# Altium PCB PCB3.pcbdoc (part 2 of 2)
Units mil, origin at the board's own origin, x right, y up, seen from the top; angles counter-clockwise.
Board outline 2248.24 x 2229.86 mil, 2 copper layers (Top Layer, Bottom Layer); 104 components, 71 nets, 405 pads, 227 vias.
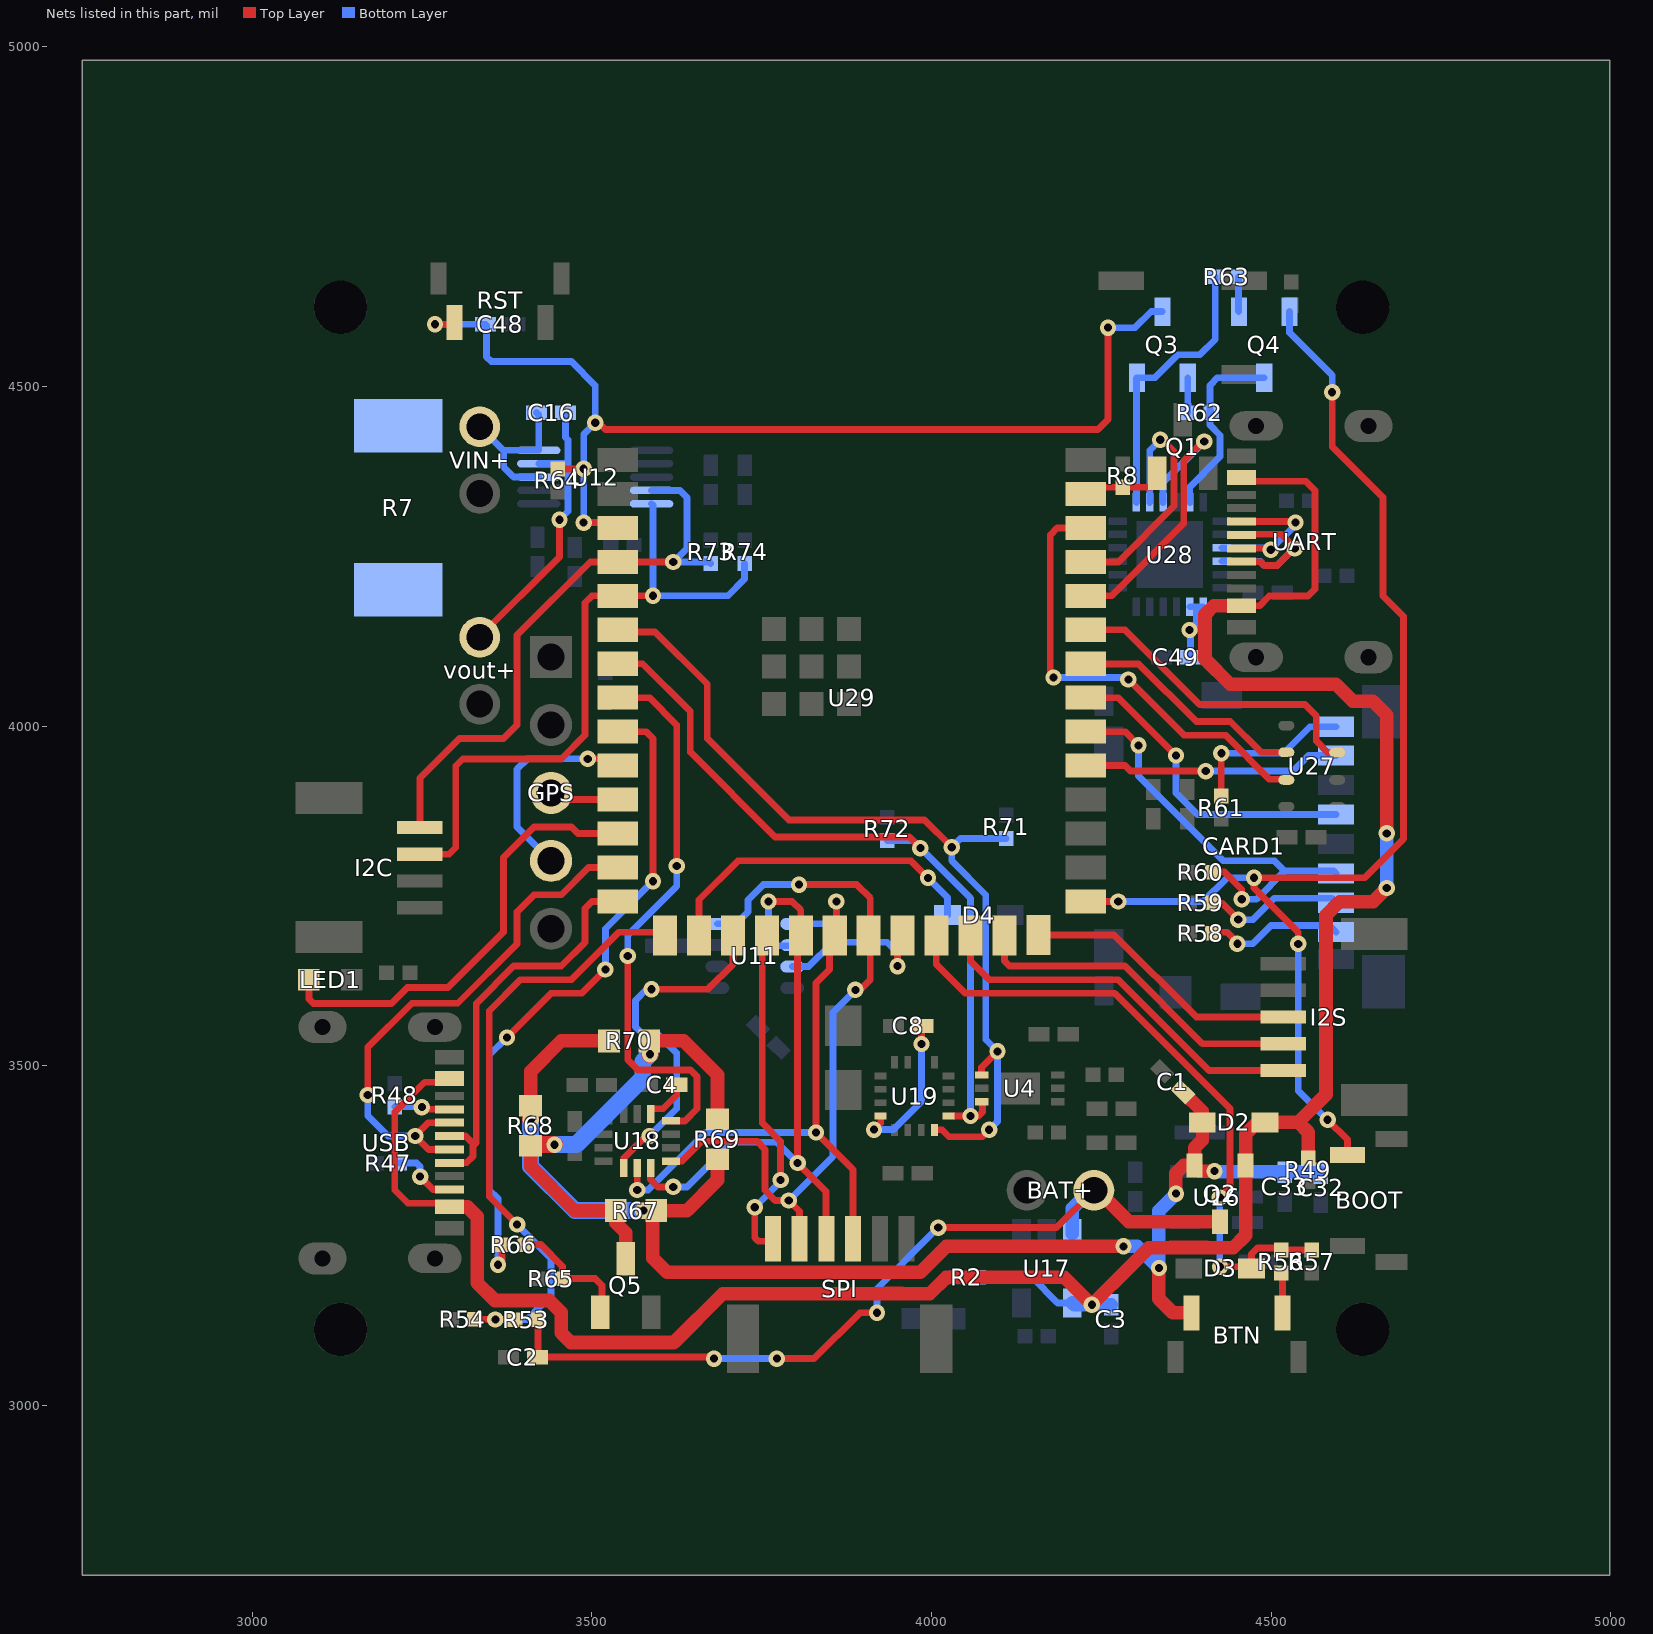
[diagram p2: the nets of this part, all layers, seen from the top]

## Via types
v1: diameter 24.02, hole 12.01, Top Layer to Bottom Layer, 222 vias
v2: diameter 24, hole 12, Top Layer to Bottom Layer, 5 vias

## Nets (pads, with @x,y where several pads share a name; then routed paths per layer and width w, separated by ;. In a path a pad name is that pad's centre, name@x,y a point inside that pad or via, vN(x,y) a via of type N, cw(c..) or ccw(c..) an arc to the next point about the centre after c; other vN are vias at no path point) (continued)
$1N23529: C4.1 U18.5 | length 69.9
  Top Layer w10: U18.5@3586.36,3428.94 3586.36,3436.5 3604.88,3436.5 3624.96,3456.58 C4.1@3624.96,3472.02
$1N25668: R48.1 USB.4 | length 82.1
  Top Layer w10: v1(3249.71,3438.84) 3252.85,3435.7 USB.4@3290.39,3435.7
  Bottom Layer w10: R48.1@3209.88,3439.46 3249.1,3439.46 v1(3249.71,3438.84)
$1N25676: R47.1 USB.10 | length 98.4
  Top Layer w10: v1(3247.06,3336.5) 3265.96,3317.59 USB.10@3290.39,3317.59
  Bottom Layer w10: R47.1@3216.92,3356.5 3242.06,3356.5 3247.06,3351.5 v1(3247.06,3336.5)
$1N26665: Q3.1 R62.2 | length 51.6
  Bottom Layer w10: Q3.1@4377.28,4512.87 4377.28,4462.06 R62.2@4377.84,4461.5
$1N26669: Q4.1 R63.2 | length 51.6
  Bottom Layer w10: R63.2@4451.92,4661.5 4451.92,4610.68 Q4.1@4452.48,4610.12
$1N33198: D4.2 U29.16 | length 491.2
  Top Layer w10: U29.16@3657.56,3691.3 3657.56,3744.18 3714.88,3801.5 3969.85,3801.5 v1(3994.87,3776.48)
  Bottom Layer w10: v1(3994.87,3776.48) 4023.72,3747.63 D4.2@4023.72,3721.5
$1N33595: BTN.1 R56.1 | length 59.4
  Top Layer w10: R56.1@4514.88,3194.46 4516.74,3192.61 BTN.1@4516.74,3135.84
$1N42658: Q5.1 R65.1 R66.2 | length 188.7
  Top Layer w10: R66.2@3401.92,3236.5 3424.88,3236.5 3456.92,3204.46 R65.1@3456.92,3186.5 3504.88,3186.5 3514.88,3176.5 3514.88,3139.53 Q5.1@3512.48,3137.13
$1N45866: Q5.3 R67.1 R68.1 R69.1 R70.1 | length 711.9
  Top Layer w20: R68.1@3409.88,3381.84 3409.88,3351.5 3474.88,3286.5 R67.1@3535.22,3286.5 3535.22,3268.76 3549.88,3254.1 Q5.3@3549.88,3215.87 ; R70.1@3584.54,3536.5 3634.88,3536.5 3684.88,3486.5 R69.1@3684.88,3421.16
  Top Layer w25: R68.1@3409.88,3381.84 3411.56,3383.51 v1(3444.88,3383.51) ; R70.1@3584.54,3536.5 3585.66,3535.38 v1(3585.66,3516.63)
  Bottom Layer w25: v1(3444.88,3383.51) 3476.9,3383.51 3574.88,3481.5 3574.88,3505.85 v1(3585.66,3516.63)
BUZZER: Q1.1 R8.2 U29.39 | length 125.6
  Top Layer w10: U29.39@4227.05,4341.69 4235.08,4341.69 4244.88,4351.5 R8.2@4281.84,4351.5 ; R8.2@4281.88,4351.46 4324.84,4351.46 4332.48,4359.1 Q1.1@4332.48,4372.13
CS: U18.12 U29.17 | length 527.5
  Top Layer w10: U18.12@3546.99,3349.22 3546.99,3363.87 3579.63,3396.5 v1(3584.88,3396.5) ; v1(3587.88,3612.5) 3670.88,3612.5 3707.56,3649.18 U29.17@3707.56,3691.3
  Bottom Layer w10: v1(3584.88,3396.5) 3624.88,3436.5 3624.88,3518.51 3596.89,3546.5 3574.88,3546.5 3564.35,3557.03 3564.35,3596.07 3580.78,3612.5 v1(3587.88,3612.5)
CS1: U11.2 U29.22 | length 243.9
  Top Layer w10: v1(3949.88,3646.5) 3949.88,3683.63 U29.22@3957.56,3691.3
  Bottom Layer w10: U11.2@3795,3645.75 3819.13,3645.75 3854.88,3681.5 3934.88,3681.5 3949.88,3666.5 v1(3949.88,3646.5)
CS2: SPI.1 U29.18 | length 504.7
  Top Layer w10: v1(3739.88,3291.5) 3739.88,3246.5 3744.88,3241.5 3762.84,3241.5 SPI.1@3766.46,3245.12 ; U29.18@3757.56,3691.3 3750.87,3684.61 3750.87,3415.51 3777.88,3388.51 v1(3777.88,3331.5)
  Bottom Layer w10: v1(3739.88,3291.5) 3777.88,3329.49 v1(3777.88,3331.5)
D+: U28.3 UART.6 UART.8 | length 252.1
  Top Layer w10: UART.6@4456.38,4261.65 4497.23,4261.65 v2(4499.39,4259.5) ; UART.8@4456.38,4301.02 4534.36,4301.02 v2(4535.88,4299.5)
  Bottom Layer w10: U28.3@4427.66,4262.34 4496.54,4262.34 v2(4499.39,4259.5) 4535.88,4296 v2(4535.88,4299.5)
D-: U28.4 UART.5 UART.7 | length 299.5
  Top Layer w10: UART.5@4456.38,4241.97 4484.41,4241.97 4489.87,4236.51 4508.91,4236.51 4533.89,4261.5 v2(4534.88,4261.5) 4534.88,4262.48 4514.88,4282.48 4457.52,4282.48 UART.7@4456.38,4281.34
  Bottom Layer w10: U28.4@4427.66,4242.65 4483.73,4242.65 4489.87,4236.51 4508.91,4236.51 4533.89,4261.5 v2(4534.88,4261.5)
DATA0: CARD1.7 U29.31 | length 381.6
  Top Layer w10: U29.31@4227.05,3941.69 4285.08,3941.69 4293.2,3933.57 v1(4403.75,3933.57)
  Bottom Layer w10: v1(4403.75,3933.57) 4531.96,3933.57 4554.88,3956.5 4595.62,3956.5 CARD1.7@4595.71,3956.4
DATA1: CARD1.8 R61.2 | length 248.1
  Top Layer w10: R61.2@4426.74,3896.94 v1(4426.74,3959.9)
  Bottom Layer w10: v1(4426.74,3959.9) 4518.29,3959.9 4557.29,3998.9 CARD1.8@4595.71,3998.9
DATA2: CARD1.1 R58.2 | length 211.3
  Top Layer w10: R58.2@4413.78,3689.9 4413.78,3695.4 4414.88,3696.5 4434.88,3696.5 4450.34,3681.05 v1(4450.34,3679.39)
  Bottom Layer w10: v1(4450.34,3679.39) 4472.77,3679.39 4499.88,3706.5 4585.72,3706.5 CARD1.1@4595.71,3696.5
DATA3: CARD1.2 R59.2 | length 208.1
  Top Layer w10: R59.2@4413.78,3739.9 4426.74,3739.9 v1(4451.74,3714.9)
  Bottom Layer w10: v1(4451.74,3714.9) 4473.29,3714.9 4504.88,3746.5 4589.02,3746.5 CARD1.2@4595.71,3739.8
DTR: Q4.3 R62.1 U28.23 | length 283.7
  Bottom Layer w10: U28.23@4380.42,4329.27 4379.88,4329.81 4379.88,4351.5 4424.88,4396.5 4424.88,4428.08 4409.88,4443.08 4409.88,4459.46 R62.1@4411.92,4461.5 4409.88,4463.54 4409.88,4501.5 4421.26,4512.87 Q4.3@4489.88,4512.87
ESP_D+: U29.14 USB.6 USB.8 | length 608.7
  Top Layer w10: USB.8@3290.39,3356.97 3315.3,3356.97 3324.82,3366.5 3324.82,3381.44 3329.88,3386.5 ; USB.6@3290.39,3396.34 3313.79,3396.34 3323.64,3386.5 3329.88,3386.5 ; U29.14@3538.07,3741.69 3500.08,3741.69 3489.88,3731.5 3489.88,3681.5 3454.88,3646.5 3384.88,3646.5 3329.88,3591.5 3329.88,3386.5
ESP_D-: U29.13 USB.5 USB.7 | length 805.5
  Top Layer w10: v1(3169.88,3456.79) 3169.88,3526.5 3235.18,3591.79 3302.5,3591.79 3389.88,3679.17 3389.88,3726.5 3414.88,3751.5 3454.88,3751.5 3495.08,3791.69 U29.13@3538.07,3791.69 ; USB.7@3290.39,3376.65 3259.73,3376.65 v1(3239.88,3396.5) 3259.41,3416.02 USB.5@3290.39,3416.02
  Bottom Layer w10: v1(3169.88,3456.79) 3169.88,3426.5 3199.88,3396.5 v1(3239.88,3396.5)
ESP_IO0: BOOT.1 Q4.2 U29.27 | length 1816.7
  Top Layer w10: U29.27@4227.05,3741.69 4274.69,3741.69 v1(4274.88,3741.5) ; v1(4539.88,3679.28) 4539.88,3696.5 4474.88,3761.5 v1(4474.88,3776.5) 4637.4,3776.5 4694.88,3833.98 4694.88,4161.5 4664.88,4191.5 4664.88,4336.5 4589.88,4411.5 v1(4589.88,4491.5) ; v1(4583.18,3420.21) 4612.33,3391.05 BOOT.1@4612.33,3368.5
  Bottom Layer w10: v1(4274.88,3741.5) 4399.88,3741.5 4434.88,3776.5 v1(4474.88,3776.5) ; Q4.2@4527.28,4610.12 4527.28,4579.1 4589.88,4516.5 v1(4589.88,4491.5) ; v1(4539.88,3679.28) 4539.88,3463.5 v1(4583.18,3420.21)
ESP_RST: C48.1 Q3.3 R64.2 RST.1 U29.3 | length 1621.3
  Top Layer w10: v1(3268.87,4591.5) 3295.43,4591.5 RST.1@3297.95,4594.02 ; R64.2@3449.88,4378.54 3487.66,4378.54 v1(3487.88,4378.76) ; v1(3487.88,4299.49) 3530.27,4299.49 U29.3@3538.07,4291.69 ; v1(3504.88,4446.5) 3509.88,4446.5 3519.88,4436.5 4244.88,4436.5 4259.88,4451.5 v1(4259.88,4586.5)
  Bottom Layer w10: v1(3268.87,4591.5) C48.1@3343.42,4591.5 3344.88,4590.04 3344.88,4543.57 3351.96,4536.5 3469.88,4536.5 3504.88,4501.5 v1(3504.88,4446.5) 3487.88,4429.49 v1(3487.88,4378.76) v1(3487.88,4299.49) ; v1(4259.88,4586.5) 4299.88,4586.5 4323.51,4610.12 Q3.3@4339.88,4610.12
ESP_RXD: U28.21 U29.36 | length 437.3
  Top Layer w10: U29.36@4227.05,4191.69 4265.08,4191.69 4371.26,4297.88 4371.26,4390.03 4400.05,4418.81 v2(4401.65,4418.81)
  Bottom Layer w10: U28.21@4341.05,4329.27 4341.05,4358.21 v2(4401.65,4418.81)
ESP_TXD: U28.20 U29.37 | length 370.7
  Top Layer w10: U29.37@4227.05,4241.69 4275.08,4241.69 4357.25,4323.86 4357.25,4404.14 4339.88,4421.5 v2(4336.88,4421.5)
  Bottom Layer w10: U28.20@4321.36,4329.27 4321.36,4405.97 v2(4336.88,4421.5)
GND: 
HEAT: R66.1 U29.9 | length 994.3
  Top Layer w10: v1(3361.84,3206.87) 3367.84,3212.87 R66.1@3367.84,3236.5 ; v1(3374.88,3541.5) 3439.88,3606.5 3484.88,3606.5 v1(3519.88,3641.5) ; U29.9@3538.07,3991.69 3579.69,3991.69 3589.88,3981.5 v1(3589.88,3771.5)
  Bottom Layer w10: v1(3361.84,3206.87) 3361.84,3304.25 3348.9,3317.19 3348.9,3515.51 v1(3374.88,3541.5) ; v1(3519.88,3641.5) 3519.88,3701.5 v1(3589.88,3771.5)
I2S1_DAT: I2S.1 U29.24 | length 564.6
  Top Layer w10: U29.24@4057.56,3691.3 4057.56,3653.82 4084.88,3626.5 4274.88,3626.5 4408.62,3492.76 I2S.1@4517.95,3492.76
I2S1_SCK: I2S.2 U29.25 | length 498.3
  Top Layer w10: U29.25@4107.56,3691.3 4107.56,3653.82 4114.88,3646.5 4284.88,3646.5 4399.25,3532.13 I2S.2@4517.95,3532.13
I2S1_WS: I2S.3 U29.26 | length 410.5
  Top Layer w10: U29.26@4157.56,3692.48 4268.9,3692.48 4389.88,3571.5 I2S.3@4517.95,3571.5
I2S_DAT: U27.7 U29.38 | length 673.8
  Top Layer w10: v1(4179.53,4071.5) 4174.88,4076.15 4174.88,4281.5 4185.08,4291.69 U29.38@4227.05,4291.69 ; v1(4289.88,4068.51) 4371.89,3986.5 4432.66,3986.5 4497.66,3921.5 4521.58,3921.5 U27.7@4522.48,3920.6
  Bottom Layer w10: v1(4179.53,4071.5) 4286.89,4071.5 v1(4289.88,4068.51)
I2S_SCK: U27.6 U29.34 | length 349.5
  Top Layer w10: U29.34@4227.05,4091.69 4227.25,4091.5 4304.88,4091.5 4389.88,4006.5 4439.88,4006.5 4484.88,3961.5 4522.18,3961.5 U27.6@4522.48,3961.2
I2S_WS: U27.3 U29.35 | length 466.7
  Top Layer w10: U29.35@4227.05,4141.69 4284.69,4141.69 4394.88,4031.5 4549.88,4031.5 4566.6,4014.78 4566.6,3977.74 4583.14,3961.2 U27.3@4597.28,3961.2
INT1: U18.4 U29.8 | length 831.9
  Top Layer w10: U29.8@3538.07,4041.69 3584.69,4041.69 3624.88,4001.5 v1(3624.88,3793.82) ; v1(3552.68,3661.5) 3552.68,3508.7 3567.75,3493.63 3645.06,3493.63 3654.88,3483.81 3654.88,3436.5 3637,3418.61 U18.4@3616.36,3418.61
  Bottom Layer w10: v1(3552.68,3661.5) 3552.68,3691.78 3624.88,3763.98 v1(3624.88,3793.82)
KEY: D3.2 R56.2 R57.1 U29.23 | length 964.4
  Top Layer w10: U29.23@4007.56,3691.3 4006.88,3690.63 4006.88,3649.5 4049.88,3606.5 4269.88,3606.5 4439.69,3436.69 4439.69,3321.02 v1(4424.54,3305.86) ; v1(4424.71,3203.95) 4468.6,3203.95 D3.2@4471.05,3201.5 4471.05,3222.66 4479.88,3231.5 4511.92,3231.5 R56.2@4514.88,3228.54 R57.1@4559.88,3228.54
  Bottom Layer w10: v1(4424.54,3305.86) 4424.54,3204.12 v1(4424.71,3203.95)
LED: LED1.1 U29.12 | length 661.9
  Top Layer w10: LED1.1@3083.4,3626.37 3083.4,3597.98 3089.88,3591.5 3204.88,3591.5 3228.27,3614.88 3288.27,3614.88 3369.88,3696.5 3369.88,3806.5 3414.88,3851.5 3469.88,3851.5 3479.69,3841.69 U29.12@3538.07,3841.69
MISO: SPI.2 U11.5 U18.1 U29.21 | length 1088.3
  Top Layer w10: U18.1@3616.36,3359.55 3632.94,3359.55 3662.08,3388.7 3742.89,3388.7 3754.88,3376.71 3754.88,3316.5 3769.88,3301.5 v1(3789.88,3301.5) 3805.83,3285.55 SPI.2@3805.83,3245.12 ; v1(3804.88,3766.5) 3889.88,3766.5 3909.88,3746.5 3909.88,3693.63 U29.21@3907.56,3691.3 3909.88,3688.98 3909.88,3626.5 3894.88,3611.5 v1(3887.88,3611.5)
  Bottom Layer w10: U11.5@3684.77,3708.74 3712.12,3708.74 3729.88,3726.5 3729.88,3744.01 3752.37,3766.5 v1(3804.88,3766.5) ; v1(3789.88,3301.5) 3854.88,3366.5 3854.88,3578.51 v1(3887.88,3611.5)
MOSI: SPI.3 U11.3 U18.14 U29.19 | length 928.3
  Top Layer w10: U18.14@3586.36,3349.22 3586.36,3332.49 3597.36,3321.5 v1(3619.88,3321.5) ; v1(3759.88,3741.5) 3794.88,3741.5 3807.56,3728.82 U29.19@3807.56,3691.3 3802.88,3686.62 v1(3802.88,3356.5) 3844.88,3314.49 3844.88,3245.44 SPI.3@3845.2,3245.12
  Bottom Layer w10: v1(3619.88,3321.5) 3639.88,3321.5 3705.42,3387.03 3772.34,3387.03 v1(3802.88,3356.5) ; v1(3759.88,3741.5) 3759.88,3686.5 3769.88,3676.5 3794.25,3676.5 U11.3@3795,3677.25
RTS: Q3.2 R63.1 U28.19 | length 414.8
  Bottom Layer w10: U28.19@4301.68,4329.27 4301.68,4512.07 Q3.2@4302.48,4512.87 4328.88,4512.87 4362.5,4546.5 4394.88,4546.5 4417.84,4569.46 R63.1@4417.84,4661.5
RXD: GPS.3 U29.11 | length 102.2
  Top Layer w10: GPS.3@3439.88,3901.5 3449.69,3891.69 U29.11@3538.07,3891.69
SCL: R72.1 U4.6 U19.1 U29.7 | length 1140
  Top Layer w10: U29.7@3538.07,4091.69 3574.69,4091.69 3644.88,4021.5 3644.88,3961.5 3769.88,3836.5 3967.37,3836.5 v1(3983.63,3820.24) ; U19.1@4024.7,3425.73 v1(4057.36,3425.73) 4069.11,3425.73 4074.88,3431.5 4074.88,3445.61 U4.6@4073.68,3446.81
  Bottom Layer w10: R72.1@3934.88,3831.46 3972.41,3831.46 v1(3983.63,3820.24) 4057.36,3746.51 v1(4057.36,3425.73)
SCL1: I2C.2 R74.2 U12.5 U29.5 | length 989.6
  Top Layer w10: I2C.2@3246.81,3811.18 3289.56,3811.18 3299.56,3821.18 3299.56,3941.18 3309.88,3951.5 3454.88,3951.5 3489.88,3986.5 3489.88,4181.5 3500.08,4191.69 U29.5@3538.07,4191.69 3589.78,4191.69 v1(3589.88,4191.8)
  Bottom Layer w10: U12.5@3587.95,4327.13 3589.88,4325.2 v1(3589.88,4191.8) 3700.18,4191.8 3724.88,4216.5 R74.2@3724.88,4239.46
SCLK: SPI.4 U11.4 U18.13 U29.20 | length 955
  Top Layer w10: v1(3566.68,3317) U18.13@3566.68,3349.22 ; v1(3859.88,3741.5) 3859.88,3693.63 U29.20@3857.56,3691.3 3849.88,3683.63 3849.88,3641.5 3829.88,3621.5 v1(3829.88,3401.5) 3884.57,3346.81 SPI.4@3884.57,3245.12
  Bottom Layer w10: v1(3566.68,3317) 3582.87,3317 3667.37,3401.5 v1(3829.88,3401.5) ; U11.4@3795,3708.74 3852.12,3708.74 3859.88,3716.5 v1(3859.88,3741.5)
SD_CMD: CARD1.3 R60.2 U29.32 | length 630
  Top Layer w10: U29.32@4227.05,3991.69 4284.69,3991.69 v1(4304.88,3971.5) ; R60.2@4413.78,3784.9 4431.48,3784.9 4456.74,3759.64 v1(4456.74,3744.9)
  Bottom Layer w10: v1(4304.88,3971.5) 4304.88,3926.5 4429.88,3801.5 4504.88,3801.5 4519.88,3786.5 ; v1(4456.74,3744.9) 4478.29,3744.9 4519.88,3786.5 ; CARD1.3@4595.71,3783.1 4592.32,3786.5 4519.88,3786.5
SD_SCLK: CARD1.5 U29.33 | length 472.1
  Top Layer w10: U29.33@4227.05,4041.69 4274.69,4041.69 v1@4359.82,3956.56
  Bottom Layer w10: v1(4359.88,3956.56) 4359.88,3901.5 4391.58,3869.8 CARD1.5@4595.71,3869.8
SDA: R71.1 U4.4 U19.16 U29.6 | length 1339.1
  Top Layer w10: U29.6@3538.07,4141.69 3541.2,4138.57 3592.81,4138.57 3669.88,4061.5 3669.88,3981.5 3789.88,3861.5 3989.88,3861.5 v1(4029.88,3821.5) ; U19.16@4004.51,3405.53 4015.85,3405.53 4026.18,3395.21 4074.56,3395.21 v1(4084.88,3405.53) ; U4.4@4073.68,3486.18 4073.68,3497.48 v1(4097.19,3520.99)
  Bottom Layer w10: v1(4084.88,3405.53) 4097.19,3417.83 v1(4097.19,3520.99) 4079.88,3538.3 4079.88,3751.5 4029.88,3801.5 v1(4029.88,3821.5) 4042.84,3834.46 R71.1@4109.88,3834.46
SDA1: I2C.1 R73.2 U12.4 U29.4 | length 870.8
  Top Layer w10: I2C.1@3246.81,3850.55 3246.81,3923.43 3304.88,3981.5 3369.88,3981.5 3389.88,4001.5 3389.88,4133.96 3497.62,4241.69 U29.4@3538.07,4241.69 3619.69,4241.69 v1(3619.88,4241.5)
  Bottom Layer w10: U12.4@3587.95,4346.81 3629.57,4346.81 3639.88,4336.5 3639.88,4261.5 v1(3619.88,4241.5) 3672.84,4241.5 R73.2@3674.88,4239.46
SETC: C8.2 U19.12 | length 223.3
  Top Layer w10: v1(3915.31,3405.79) 3925.25,3415.73 U19.12@3925.25,3425.72 ; v1(3985.31,3531.83) 3985.31,3556.45 C8.2@3987.22,3558.36
  Bottom Layer w10: v1(3915.31,3405.79) 3944.17,3405.79 3985.31,3446.93 v1(3985.31,3531.83)
TXD: GPS.4 U29.10 | length 314.3
  Top Layer w10: v1(3493.88,3951.66) 3528.03,3951.66 U29.10@3538.03,3941.66
  Bottom Layer w10: GPS.4@3439.88,3801.5 3389.88,3851.5 3389.88,3936.5 3405.04,3951.66 v1(3493.88,3951.66)
V_OUT: BTN.2 C1.2 C32.2 C33.2 D2.1 Q2.2 R67.2 R68.2 R69.2 R70.2 U16.1 | length 2067.2
  Top Layer w20: R68.2@3409.88,3441.16 3409.88,3491.5 3454.88,3536.5 R70.2@3525.22,3536.5 ; R67.2@3589.88,3276.16 3589.88,3216.5 3610.88,3195.5 3983.45,3195.48 4021.81,3233.84 v1(4282.58,3233.84) ; R67.2@3594.54,3286.5 3639.88,3286.5 3684.88,3331.5 R69.2@3684.88,3361.84 ; v1(4334.88,3201.97) 4334.88,3156.5 4355.54,3135.84 BTN.2@4382.88,3135.84 ; v1(4359.88,3311.5) 4359.88,3341.5 4371.42,3353.04 Q2.2@4387.28,3353.04 ; C1.2@4370.06,3461.32 4398.72,3432.66 D2.1@4398.72,3416.5 4398.72,3390.33 4387.28,3378.9 Q2.2@4387.28,3353.04 ; v1(4416.7,3344.69) 4395.63,3344.69 Q2.2@4387.28,3353.04
  Top Layer w25: v1(3409.88,3420.53) R68.2@3409.88,3441.16 ; v1(3575.76,3286.5) R67.2@3594.54,3286.5
  Bottom Layer w20: v1(4282.58,3233.84) 4303.01,3233.84 v1(4334.88,3201.97) 4334.88,3286.5 v1(4359.88,3311.5) ; v1(4416.7,3344.69) 4417.49,3343.9 U16.1@4465.3,3343.9 4571.02,3343.9 C32.2@4573.42,3341.5
  Bottom Layer w25: v1(3409.88,3420.53) 3409.88,3351.5 3474.88,3286.5 v1(3575.76,3286.5)
VBAT: BAT+.2 C2.1 Q2.3 R53.2 U17.3 | length 1288
  Top Layer w10: R53.2@3420.54,3125.81 3420.54,3071.39 C2.1@3419.96,3070.81 3677.71,3070.81 v1(3679.88,3068.64) ; v1(3772.36,3068.64) 3827.02,3068.64 3894.46,3136.07 v1(3919.88,3136.07) ; v1(4009.88,3261.5) 4184.08,3261.5 BAT+.2@4239.08,3316.5
  Top Layer w20: BAT+.2@4239.08,3321.5 4290.62,3269.96 Q2.3@4424.88,3269.96
  Bottom Layer w10: v1(3679.88,3068.64) v1(3772.36,3068.64) ; v1(3919.88,3136.07) 3919.88,3171.5 v1(4009.88,3261.5)
  Bottom Layer w20: U17.3@4207.32,3252.44 4207.32,3289.74 BAT+.2@4239.08,3321.5
VBAT_AD: R53.1 R54.2 U29.15 | length 922.5
  Top Layer w10: R54.2@3326.92,3126.5 v1@3357.55,3126.5 ; v1(3357.92,3126.13) v1@3357.55,3126.5 ; R53.1@3386.46,3125.81 3385.77,3126.5 v1@3357.55,3126.5 ; v1(3389.88,3266.21) 3389.88,3266.44 3348.9,3307.5 3348.9,3580.51 3394.88,3626.5 3469.88,3626.5 3539.88,3696.5 3602.37,3696.5 U29.15@3607.56,3691.3
  Bottom Layer w10: v1(3357.92,3126.13) 3404.51,3126.13 3439.88,3161.5 3439.88,3216.21 v1(3389.88,3266.21)
VIN: C3.2 C49.2 D2.2 Q2.1 R2.1 R49.2 U17.4 U28.7 U28.8 UART.2 UART.11 USB.2 USB.11 | length 3851.7
  Top Layer w10: USB.11@3290.39,3292 3284.91,3297.48 3228.9,3297.48 3209.88,3316.5 3209.88,3431.53 3253.86,3475.51 3284.91,3475.51 USB.2@3290.39,3480.98 ; v1(4379.88,4141.5) 4402.29,4141.5 4402.68,4141.11 ; UART.2@4456.38,4177.01 4482.78,4177.01 4497.26,4191.5 4554.42,4191.5 4564.42,4201.5 4564.42,4346.96 4550.86,4360.52 4461.85,4360.52 UART.11@4456.38,4365.99
  Top Layer w20: USB.11@3290.39,3292 3316.79,3292 3330.93,3277.86 3330.93,3180.45 3357.26,3154.12 3437.26,3154.12 3454.88,3136.5 3454.88,3106.5 3469.03,3092.36 3620.81,3092.36 3692.51,3164.06 3932.86,3164.06 3933.29,3164.49 3956.48,3164.49 3956.91,3164.06 3997.45,3164.06 4021.92,3188.54 4195.53,3188.54 v1(4236.11,3147.96) 4293.99,3205.84 4294.17,3205.84 4310.57,3222.24 4310.57,3222.43 4320.09,3231.94 4352.11,3231.94 4352.41,3232.25 4405.02,3232.25 4405.33,3231.94 4444.44,3231.94 4462.48,3249.99 Q2.1@4462.48,3353.04 4462.48,3399.1 4479.88,3416.5 D2.2@4491.05,3416.5 4539.88,3416.5 ; UART.2@4456.38,4177.01 4415.4,4177.01 4402.68,4164.29 4402.68,4141.11 4402.68,4098.7 4439.88,4061.5 4595.47,4061.5 4620.47,4036.5 4649.88,4036.5 4670.31,4016.08 v1(4670.31,3841.92) ; R49.2@4554.88,3363.54 4554.88,3401.5 4539.88,3416.5 ; v1(4670.31,3761.5) 4650.31,3741.5 4600.79,3741.5 4580.79,3721.5 4580.79,3457.41 4539.88,3416.5
  Bottom Layer w10: R2.1@4068.92,3188.5 4147.88,3188.5 4185.83,3150.55 U17.4@4207.32,3150.55 ; U28.8@4380.42,4175.72 4390.16,4175.72 ; C49.2@4381.34,4101.5 4381.34,4140.04 v1(4379.88,4141.5) 4390.16,4151.77 4390.16,4175.72 ; U28.7@4400.1,4175.72 4390.16,4175.72
  Bottom Layer w20: U17.4@4207.32,3150.55 4209.91,3147.96 v1(4236.11,3147.96) C3.2@4264.88,3147.96 ; v1(4670.31,3761.5) v1(4670.31,3841.92)
VIN+: C16.2 R7.2 U12.8 U12.10 VIN+.1 | length 241
  Bottom Layer w10: VIN+.1@3334.88,4440.7 3369.71,4405.87 ; C16.2@3418.42,4461.5 3421.81,4458.11 U12.10@3421.81,4405.87 3369.71,4405.87 ; U12.8@3421.81,4366.5 3384.88,4366.5 3369.88,4381.5 3369.88,4405.7 3369.71,4405.87
VOUT+: C16.1 R7.1 U12.9 vout+.1 | length 430.2
  Top Layer w10: vout+.1@3334.88,4130.7 3334.88,4131.5 3452.34,4248.96 v1(3452.34,4303.62)
  Bottom Layer w10: U12.9@3421.81,4386.18 3422.13,4386.5 3462.81,4386.5 3464.88,4388.57 ; v1(3452.34,4303.62) 3464.88,4316.16 3464.88,4388.57 ; C16.1@3461.34,4461.5 3461.34,4425.04 3464.88,4421.5 3464.88,4388.57
pads on no net: BAT+.1 BOOT.2 BOOT.3 BOOT.4 BTN.3 BTN.4 BUZZER1.3 C1.1 C2.2 C3.1 C4.2 C5.1 C6.1 C7.2 C9.1 C14.1 C15.1 C17.1 C18.1 C19.1 C20.1 C21.1 C22.1 C32.1 C33.1 C36.1 C37.1 C42.1 C43.1 C44.2 C45.2 C46.2 C47.2 C48.2 C49.1 CARD1.6 CARD1.9 CARD1.10 CARD1.11 CARD1.12 CARD1.13 CARD1.14 CARD1.15 CARD1.16 CARD1.17 CARD1.18 GPS.2 GPS.5 I2C.3 I2C.5 I2C.6 I2S.4 I2S.6 I2S.7 Q1.2 Q5.2 R1.2 R8.1 R40.1 R42.2 R43.2 R47.2 R48.2 R49.1 R54.1 R55.1 R57.2 R65.2 RST.2 RST.3 RST.4 SCREW1.1 SCREW2.1 SCREW3.1 SCREW4.1 SPI.5 SPI.7 SPI.8 U4.3 U4.7 U11.1 U11.7 U12.1 U12.2 U12.7 U16.2 U16.4 U17.2 U18.2 U18.3 U18.6 U18.7 U18.9 U18.10 U18.11 U19.3 U19.5 U19.6 U19.7 U19.9 U19.11 U19.14 U19.15 U27.1 U27.2 U27.5 U28.1 U28.2 U28.9 U28.10 U28.11 U28.12 U28.13 U28.14 U28.15 U28.16 U28.17 U28.18 U28.22 U28.24 U28.25 U29.1 U29.28 U29.29 U29.30 U29.40 U29.41 UART.1 UART.3 UART.9 UART.12 UART.13 UART.14 USB.1 USB.3 USB.9 USB.12 USB.13 USB.14 VIN+.2 vout+.2
copper on no net: | length 1082.3
  Top Layer w10: 3474.88,3375.04 3474.88,3346.5 v1(3484.88,3336.5) 3504.88,3336.5 3512.94,3344.55 3512.94,3359.55 3516.99,3359.55 ; 3521.34,3471.5 3521.34,3445.04 3529.88,3436.5 3544.88,3436.5 3546.99,3434.39 3546.99,3428.94 3546.99,3404.39 v1(3549.88,3401.5) 3566.68,3418.3 3566.68,3428.94 3566.68,3443.6 3582.04,3458.95 3582.04,3472.02 ; 3925.25,3445.41 3938.79,3445.41 3949.88,3456.5 3949.88,3476.5 3941.6,3484.78 3925.25,3484.78
  Bottom Layer w10: 3334.88,4342.3 3339.39,4346.81 3421.81,4346.81 ; v1(3549.88,3401.5) v1(3484.88,3336.5) 3534.88,3336.5 3554.88,3356.5 3584.88,3356.5 3644.88,3416.5 3759.88,3416.5 v1(3774.88,3431.5) ; 4350.89,4252.5 4380.41,4282.02 4427.66,4282.02 ; 4465.3,3306.5 4513.42,3306.5 4519.88,3300.04
  Bottom Layer w20: 4140.68,3321.5 4169.84,3292.34 4169.84,3252.44
  other v1: 3864.49,3057.17 3230.51,3066.87 3261.36,3066.87 3889.88,3076.5 3229.88,3096.5 3261.89,3096.5 3809.88,3096.5 3909.88,3101.5 4104.88,3101.5 4209.88,3101.5 3549.88,3124.89 3779.88,3131.5 3832.29,3131.5 4168.03,3130.67 3619.88,3136.5 4304.88,3141.5 4564.88,3141.5 3559.88,3156.5 3634.88,3161.5 3584.18,3175.81 3392.71,3186.5 4609.88,3186.5 3110.51,3281.87 3141.36,3281.87 4622.61,3291.52 3924.87,3307.78 3109.88,3311.5 3141.89,3311.5 4321.27,3312.47 4622.61,3330.49 3924.87,3369.63 4335.51,3406.87 3879.88,3411.5 4329.88,3451.5 3085.51,3461.87 3116.36,3461.87 3774.88,3471.5 3959.88,3471.5 3084.88,3491.5 3116.89,3491.5 4199.88,3511.5 4649.88,3511.5 4679.7,3511.5 3911.99,3518.49 4024.88,3536.5 4251.36,3541.87 4649.88,3556.5 4683.09,3556.5 4234.88,3561.5 4266.89,3561.5 3774.88,3586.5 3964.88,3596.5 4410.24,3595.65 3939.88,3616.5 3993.83,3616.5 4409.88,3621.5 4329.88,3681.5 3123.1,3761.87 3153.96,3761.87 4279.88,3776.5 4124.88,3786.5 3122.48,3791.5 3154.48,3791.5 4084.88,3796.5 4169.88,3796.5 4289.88,3816.5 4334.88,3816.5 4149.88,3821.5 4285.08,3903.1 4389.22,3905.68 4559.88,3905.71 4484.88,4001.5 3170.51,4031.87 3201.36,4031.87 3169.88,4061.5 3201.89,4061.5 4015.51,4061.87 4046.36,4061.87 4014.88,4091.5 4046.89,4091.5 4329.88,4141.5 4624.88,4166.5 4010.51,4171.87 4041.36,4171.87 4009.88,4201.5 4041.89,4201.5 4339.88,4221.5 4382.27,4221.5 3925.51,4221.87 3956.36,4221.87 4689.88,4246.5 3924.88,4251.5 3956.89,4251.5 4385.58,4257.5 4634.22,4271.5 3795.51,4286.87 3826.36,4286.87 4689.88,4301.5 3135.51,4301.87 3166.36,4301.87 3794.88,4316.5 3826.89,4316.5 4634.88,4316.5 4020.51,4326.87 4051.36,4326.87 3134.88,4331.5 3166.89,4331.5 4019.88,4356.5 4051.89,4356.5 3639.88,4406.5 4524.88,4476.5 4625.51,4496.87 4656.36,4496.87 4624.88,4526.5 4656.89,4526.5 4288.09,4559.9 4459.2,4563.1 4489.88,4563.1 3475.51,4571.87 3506.36,4571.87 3474.88,4601.5 3506.89,4601.5 4384.88,4621.5 4369.88,4659.98

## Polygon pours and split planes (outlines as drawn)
VIN+ on Bottom Layer (solid, remove dead copper, pour order 2): 3139.88,4381.5 3369.88,4381.5 3369.88,4487.99 3139.88,4487.99
no net on Top Layer (solid, remove dead copper): 3044.88,3026.5 4719.88,3026.5 4719.88,4701.5 3044.88,4701.5
VOUT+ on Bottom Layer (solid, remove dead copper, pour order 4): 3147.12,4096.5 3369.88,4096.5 3369.88,4241.5 3147.12,4241.5
no net on Bottom Layer (solid, remove dead copper, pour order 6): 3044.88,3026.5 4719.88,3026.5 4719.88,4701.5 3044.88,4701.5

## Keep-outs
Board Outline Layer:
  lines w10: 4229.88,4696.5 4230.03,4696.65 4670.03,4696.65 cw(c4664.2,4645.82) 4715.03,4651.65 ; 4229.89,4696.65 4229.89,4456.5 4219.88,4456.5 3534.88,4456.5 3534.88,4696.5 3526.16,4696.5 3526.01,4696.65 3095.23,4696.65 ccw(c3101.06,4645.82) 3050.23,4651.65 3050.23,4391.5 3050.03,3376.38 3050.23,3076.85 ccw(c3101.06,3082.68) 3095.23,3031.85 4670.03,3031.85 ccw(c4664.2,3082.68) 4715.03,3076.85 4715.03,3626.5 4715.03,4061.97 ; 4714.58,4651.65 4714.58,4318.63 4714.88,4061.97
Multi-Layer:
  region: 3519.88,3568.87 3464.93,3568.87 3379.88,3486.31 3379.88,3431.5 3359.99,3431.5 3359.99,3501.11 3455.02,3591.5 3519.88,3591.5
  region: 3379.8,3401.5 3379.8,3341.84 3460.07,3256.5 3524.88,3256.5 3524.88,3231.6 3450.03,3231.6 3359.88,3326.38 3359.88,3401.5
  region: 3715.09,3431.13 3715.09,3491.05 3635.26,3566.4 3575.33,3566.4 3575.33,3591.52 3645.34,3591.52 3739.88,3501.46 3739.88,3431.13
  region: 3609.99,3256.41 3642.26,3256.41 3714.88,3331.5 3714.88,3376.05 3740.01,3376.05 3740.01,3321.59 3654.37,3231.5 3609.99,3231.5
  region: 3464.93,3568.87 3632.51,3568.87 3715.09,3491.05 3714.88,3331.5 3642.26,3256.41 3460.07,3256.99 3379.8,3341.84 3379.88,3486.31

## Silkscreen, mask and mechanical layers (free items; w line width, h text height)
Mechanical Layer:
  lines w1: 3359.88,3326.38 3450.03,3231.6 3524.88,3231.6 3524.88,3256.5 3460.07,3256.5 3379.8,3341.84 3379.8,3401.5 3359.88,3401.5 3359.88,3326.38 ; 3359.99,3431.5 3379.88,3431.5 3379.88,3486.31 3464.93,3568.87 3519.88,3568.87 3519.88,3591.5 3455.02,3591.5 3359.99,3501.11 3359.99,3431.5 ; 3575.33,3566.4 3635.26,3566.4 3715.09,3491.05 3715.09,3431.13 3739.88,3431.13 3739.88,3501.46 3645.34,3591.52 3575.33,3591.52 3575.33,3566.4 ; 3609.99,3231.5 3654.37,3231.5 3740.01,3321.59 3740.01,3376.05 3714.88,3376.05 3714.88,3331.5 3642.26,3256.41 3609.99,3256.41 3609.99,3231.5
